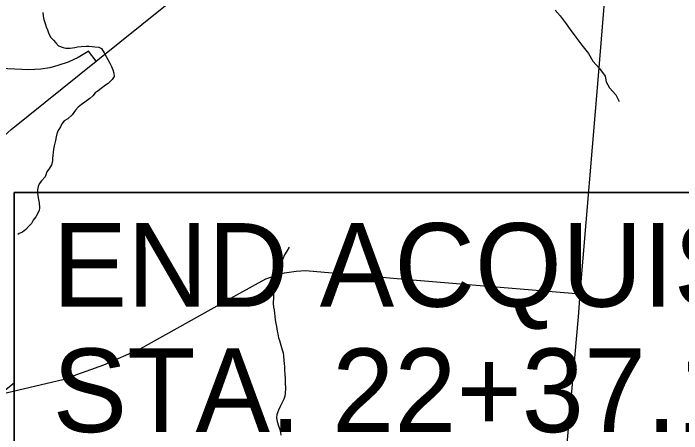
# Model space of a CAD drawing. Extents: x 0 to 34, y 0 to 22.
# Drawn here: x 5.853 to 6.973, y 19.475 to 20.179 of the extents above; entities that cross this region are included whole.
import ezdxf

# ---------------------------------------------------------------- set-up
doc = ezdxf.new("R2010")
doc.units = 0
for name, color, linetype in [('GM_X_City_Street', 7, 'Continuous'), ('GM_X_Interchange_Ramps', 7, 'Continuous'), ('GM_X_Interstate_Route', 7, 'Continuous'), ('GM_X_Minor_River', 7, 'Continuous'), ('RD_P_Text', 7, 'Continuous'), ('SH_Masking', 7, 'Continuous')]:
    doc.layers.add(name, color=color, linetype=linetype)

msp = doc.modelspace()

# ---------------------------------------------------------------- linework, layer by layer
at = {"layer": 'GM_X_City_Street'}
for points in [[(6.7405, 19.0079), (6.7405, 19.0079), (6.7657, 19.288), (6.7742, 19.3827), (6.7997, 19.6706), (6.8028, 19.7088), (6.8332, 20.0742), (6.8703, 20.5257), (6.8776, 20.6185)], [(5.8218, 19.5387), (5.9387, 19.566), (5.9456, 19.5689), (6.005, 19.5899), (6.0658, 19.617), (6.2275, 19.7075), (6.2587, 19.7248), (6.2764, 19.7338), (6.2999, 19.742), (6.3076, 19.7442), (6.3269, 19.7471), (6.3429, 19.7478), (6.5216, 19.7326), (6.5217, 19.7326)], [(6.5217, 19.7326), (6.7225, 19.7156), (6.7225, 19.7156)], [(6.7225, 19.7156), (6.8028, 19.7088)]]:
    msp.add_lwpolyline(points, dxfattribs=at)
at = {"layer": 'GM_X_Interchange_Ramps'}
msp.add_lwpolyline([(5.9922, 20.0984), (5.9792, 20.1151), (5.976, 20.113), (5.9617, 20.1048), (5.945, 20.0968), (5.9281, 20.0912), (5.9143, 20.0872), (5.8995, 20.085), (5.8791, 20.0839), (5.7604, 20.0896), (5.753, 20.09), (5.7472, 20.0902)], dxfattribs=at)
at = {"layer": 'GM_X_Interstate_Route'}
msp.add_lwpolyline([(5.8297, 19.9667), (5.8374, 19.973), (5.8497, 19.9841), (5.9922, 20.0984), (6.1844, 20.2537), (6.2121, 20.2744), (6.2584, 20.306), (6.2797, 20.318), (6.2913, 20.3246)], dxfattribs=at)
at = {"layer": 'GM_X_Minor_River'}
for points in [[(5.9026, 20.1802), (5.9032, 20.1737), (5.9046, 20.1684), (5.9064, 20.1619), (5.9081, 20.1561), (5.9103, 20.1511), (5.9125, 20.1458), (5.9158, 20.1389), (5.9206, 20.1338), (5.9243, 20.1292), (5.9291, 20.1245), (5.9367, 20.1217), (5.9412, 20.1205), (5.9484, 20.1203), (5.9564, 20.1217), (5.961, 20.1227), (5.9667, 20.123), (5.9751, 20.1236), (5.9804, 20.1235), (5.9853, 20.123), (5.9898, 20.1225), (5.9963, 20.122), (6.0012, 20.1196), (6.0052, 20.1123), (6.0089, 20.1066), (6.0118, 20.1012), (6.0151, 20.095), (6.018, 20.0896), (6.0202, 20.0839), (6.0216, 20.0785), (6.0222, 20.0728), (6.0191, 20.0676), (6.0121, 20.0609), (6.0075, 20.0583), (6.0002, 20.0527), (5.9956, 20.0486), (5.9902, 20.0453), (5.9863, 20.0405), (5.9813, 20.036), (5.9732, 20.0301), (5.9674, 20.026), (5.962, 20.0215), (5.9577, 20.0163), (5.9519, 20.0088), (5.9445, 20.0021), (5.9387, 19.9988), (5.9345, 19.9936), (5.9325, 19.9887)], [(6.7608, 20.184), (6.7693, 20.1743), (6.7793, 20.1611), (6.7862, 20.1514), (6.7954, 20.1387), (6.8057, 20.1255), (6.8164, 20.1115), (6.8241, 20.0984), (6.8348, 20.0864), (6.8443, 20.0736), (6.846, 20.0641), (6.8518, 20.0537), (6.8626, 20.042), (6.868, 20.0308)], [(5.9325, 19.9887), (5.9297, 19.9842), (5.927, 19.9789), (5.9253, 19.9717), (5.924, 19.9656), (5.9228, 19.9611), (5.9219, 19.9565), (5.9207, 19.9509), (5.9202, 19.9459), (5.9197, 19.9406), (5.9192, 19.9357), (5.9192, 19.9311), (5.9175, 19.9247), (5.914, 19.9194), (5.9097, 19.913), (5.9065, 19.9051), (5.9003, 19.8984), (5.8964, 19.8932), (5.8951, 19.8886), (5.8939, 19.8829), (5.8938, 19.878), (5.8941, 19.873), (5.8955, 19.8669), (5.8965, 19.8612), (5.8971, 19.8532), (5.8966, 19.8483), (5.8911, 19.8377), (5.8868, 19.8321), (5.8836, 19.8268), (5.879, 19.8216), (5.8743, 19.8168), (5.8685, 19.8123), (5.8632, 19.8098), (5.8606, 19.8083)], [(6.3152, 19.787), (6.3116, 19.7806), (6.3073, 19.7743), (6.3049, 19.7678), (6.3025, 19.761), (6.3005, 19.7542), (6.2988, 19.7474), (6.2976, 19.7429), (6.2964, 19.738), (6.2955, 19.7334), (6.2906, 19.7153), (6.2893, 19.7084), (6.2888, 19.7035), (6.2886, 19.6925), (6.2892, 19.6868), (6.2899, 19.6814), (6.2906, 19.6765), (6.2912, 19.6711), (6.2919, 19.6654), (6.2929, 19.6593), (6.2939, 19.654), (6.2953, 19.6463), (6.2963, 19.6417), (6.2977, 19.6353), (6.2991, 19.6307), (6.3012, 19.623), (6.3037, 19.6154), (6.3052, 19.61), (6.3058, 19.6047), (6.3064, 19.5974), (6.3067, 19.5921), (6.3073, 19.5868), (6.3076, 19.581), (6.3078, 19.5746), (6.3085, 19.5673), (6.3087, 19.5601), (6.3089, 19.5502), (6.3087, 19.5426), (6.3082, 19.5377), (6.3066, 19.5328), (6.3027, 19.5249), (6.3003, 19.52), (6.2975, 19.5139), (6.2947, 19.5068), (6.2942, 19.5011), (6.2952, 19.4953), (6.2974, 19.4877), (6.2995, 19.4816), (6.3006, 19.477), (6.3012, 19.4724)]]:
    msp.add_lwpolyline(points, dxfattribs=at)
at = {"layer": 'RD_P_Text'}
msp.add_lwpolyline([(5.8549, 19.8788), (7.7843, 19.8788), (7.7843, 19.4106), (5.8549, 19.4106)], close=True, dxfattribs=at)
msp.add_lwpolyline([(5.8549, 19.4106), (5.2002, 19.0384), (5.8549, 19.5598), (5.8549, 19.4106)], dxfattribs=at)
at = {"layer": 'SH_Masking'}
msp.add_lwpolyline([(7.7843, 19.8788), (5.8549, 19.8788), (5.8549, 19.4106), (7.7843, 19.4106)], close=True, dxfattribs=at)

# ---------------------------------------------------------------- texts
at = {"layer": 'RD_P_Text'}
for s, p in [('END ACQUISITION', (5.9191, 19.6874)), ('STA. 22+37.14', (5.9191, 19.4774))]:
    msp.add_text(s, height=0.14, dxfattribs=at).set_placement(p)

doc.saveas('drawing.dxf')
